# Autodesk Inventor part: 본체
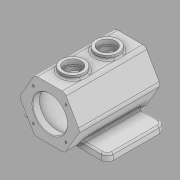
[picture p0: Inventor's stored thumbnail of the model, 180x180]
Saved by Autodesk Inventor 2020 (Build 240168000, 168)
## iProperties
Created: 2021-06
Part Number: 본체
Material: 일반
Document SubType Name: Modeling
Designer: MIRAE
Density: 1 g/cm^3
Appearance: 기본값
Author: MIRAE
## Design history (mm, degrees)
sketch "스케치1" dims "d0" = 105
  geometry: L1 (52.5, 0)-(26.25, -45.466); L2 (26.25, -45.466)-(-26.25, -45.466); L3 (-26.25, -45.466)-(-52.5, 0); L4 (-52.5, 0)-(-26.25, 45.466); L5 (-26.25, 45.466)-(26.25, 45.466); L6 (26.25, 45.466)-(52.5, 0); 3 further points
  constraints: 12 end point, 2 coincident, 1 horizontal, 1 horizontal alignment, 15 other
extrude "돌출1" new body sketch "스케치1" stored distance "d1" = 140; taper "d2" = 0 deg
node "작업 평면1"
sketch "스케치2"
  geometry: L1 (75, 45)-(-75, 45); L2 (-75, 45)-(-75, -55); L3 (-75, -55)-(75, -55); L4 (75, -55)-(75, 45); L5 (26.25, 70)-(52.5, 70) reference; L6 (52.5, -70)-(26.25, -70) reference; 3 further points
  constraints: 8 end point, 2 midpoint, 2 parallel, 1 horizontal, 1 perpendicular, 1 vertical alignment
  dimensions: "d4" = 150 distance of L2.end L3.end; "d6" = 25 distance between parallel lines of L5 L1; "d7" = 15 distance between parallel lines of L6 L3
extrude "돌출2" join sketch "스케치2" distance "d8" = 12; taper "d9" = 0 deg
fillet "모깎기1" dims "d10" = 8
fillet "모깎기2" dims "d11" = 10
fillet "모깎기3" dims "d12" = 3
fillet "모깎기4" dims "d13" = 3
sketch "스케치3"
  geometry: L1 (30, -70)-(30, -58); L2 (30, -58)-(37.5, -58); L3 (37.5, -58)-(37.5, 58); L4 (37.5, 58)-(30, 58); L5 (30, 58)-(30, 70); L6 (30, 70)-(0, 70); L7 (0, 70)-(0, -70); L8 (0, -70)-(30, -70); L9 (41.466, -70)-(4, -70) reference; 2 further points
  constraints: 16 end point, 6 perpendicular, 2 collinear, 2 point on line, 1 coincident, 1 midpoint, 1 vertical
  dimensions: "d14" = 60 diameter of L5 L7; "d15" = 75 diameter of L3 L7; "d16" = 12 distance of L1.start L1.end
revolve "회전1" sketch "스케치3" stored, may be unused: angle "d17" = 90 deg
fillet "모깎기5" dims "d18" = 5
chamfer "모따기1" distance "d19" = 1; stored, may be unused: second distance "d20" = 2, angle "d21" = 45 deg
node "작업 평면2"
sketch "스케치4"
  geometry: L1 (-21.631, 70)-(21.631, 70) reference; C1 r 20 at (0, 30); C2 r 20 at (0, -30); 1 further point
  constraints: 2 centre point, 2 vertical alignment
  dimensions: "d23" = 40 diameter of C1; "d24" = 40 distance from line of C1.centre L1; "d25" = 40 diameter of C2; "d26" = 60 distance of C2.centre C1.centre
extrude "돌출3" join sketch "스케치4" stored distance "d27" = 12; taper "d28" = 0 deg
sketch "스케치5"
  geometry: C1 r 20 at (0, 0) reference; 2 further points
  constraints: 1 coincident
hole "구멍1" sketch "스케치5" at (0, 0) diameter "d29" = 25; stored, may be unused: countersink angle "d33" = 90 deg, drill point angle "d35" = 118 deg; dims "d30" = 6, "d31" = 30, "d32" = 8, "d34" = 8
sketch "스케치6"
  geometry: C1 r 20 at (0, 0) reference; 2 further points
  constraints: 1 coincident
hole "구멍2" sketch "스케치6" at (0, 0) diameter "d36" = 25; stored, may be unused: countersink angle "d40" = 90 deg, drill point angle "d42" = 118 deg; dims "d37" = 6, "d38" = 30, "d39" = 8, "d41" = 8
chamfer "모따기2" distance "d43" = 1; stored, may be unused: second distance "d44" = 2, angle "d45" = 45 deg
sketch "스케치7"
  geometry: L1 (0, 0)-(0, 40); L2 (0, 0)-(-28.284, 28.284); A1 r 40 centre (0, 0) between (0, 40) and (-28.284, 28.284); 4 further points
  constraints: 4 end point, 2 point on circle, 1 centre point, 1 coincident, 1 vertical, 5 other
  dimensions: "d46" = 80 diameter of A1; "d47" = 45 deg angle of L1 L2; "d50" = 360 deg dimension on point (0, 0) L2.end (derived)
hole "구멍3" sketch "스케치7" at (-28.284, 28.284), (-28.284, -28.284), (28.284, -28.284), (28.284, 28.284) diameter "d52" = 3.45873; stored, may be unused: countersink angle "d56" = 90 deg, drill point angle "d58" = 118 deg; dims "d53" = 8, "d54" = 30, "d55" = 8, "d57" = 10
sketch "스케치8" dims "d59" = 80
  geometry: 6 further points
  constraints: 2 vertical alignment, 1 coincident, 7 other
  dimensions: "d62" = 360 deg dimension on point (0, 0) point (0, 40) (derived)
hole "구멍4" sketch "스케치8" at (0, 40), (-40, 0), (0, -40), (40, 0) diameter "d64" = 3.45873; stored, may be unused: countersink angle "d68" = 90 deg, drill point angle "d70" = 118 deg; dims "d65" = 8, "d66" = 30, "d67" = 8, "d69" = 10
fillet "모깎기6" dims "d71" = 3
sketch "스케치9"
  geometry: L1 (-57.998, 25.739)-(-57.998, -15.739); L2 (-57.998, -15.739)-(-64.002, -15.739); L3 (-64.002, -15.739)-(-64.002, 25.739); L4 (-64.002, 25.739)-(-57.998, 25.739); L5 (-64.002, 25.739)-(-57.998, -15.739); L6 (-75, 45)-(-75, -35) reference; L7 (-65, -45)-(-32.293, -45) reference; 2 further points
  constraints: 2 end point, 1 midpoint, 2 other
  dimensions: "d72" = 14 distance from line of point (-61, 5) L6; "d73" = 50 distance from line of point (-61, 5) L7
feature "엠보싱1" sketch "스케치9" dims "d0" = 105, "d74" = 0.5, "d75" = 0
node "솔리드1"
feature "A9D066F2-1C7D-4E18-AEED-F7BC21143FA4" dims "d29" = 25, "d30" = 6, "d31" = 30, "d32" = 8, "d33" = 90 deg, "d34" = 8, "d35" = 118 deg
other parameters: "d22" = 52.5
